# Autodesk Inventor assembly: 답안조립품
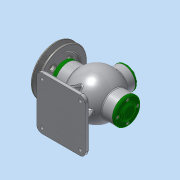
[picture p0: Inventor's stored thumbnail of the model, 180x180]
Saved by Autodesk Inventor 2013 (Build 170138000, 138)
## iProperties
Created: 2018-06
Part Number: 답안조립품
Document SubType Name: Assembly
Designer: Administrator
Author: Administrator
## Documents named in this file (19)
- C:\Users\Administrator\Desktop\480612V1001\답안조립품.iam
- C:\Users\Administrator\Desktop\480612V1001\본체.ipt
- C:\Users\Administrator\Desktop\480612V1001\V-벨트풀리.ipt
- C:\Users\Administrator\Desktop\480612V1001\너트 M8.ipt
- C:\Users\Administrator\Desktop\480612V1001\뒤커버.ipt
- C:\Users\Administrator\Desktop\480612V1001\멈춤링 15x1.ipt
- C:\Users\Administrator\Desktop\480612V1001\멈춤링 35x1.6.ipt
- 멈춤링 35x1.6.ipt
- C:\Users\Administrator\Desktop\480612V1001\베어링 6202.ipt
- 베어링 6202.ipt
- C:\Users\Administrator\Desktop\480612V1001\볼트 M4x12.ipt
- C:\Users\Administrator\Desktop\480612V1001\볼트 M4x16.ipt
- C:\Users\Administrator\Desktop\480612V1001\부시.ipt
- C:\Users\Administrator\Desktop\480612V1001\상부커버.ipt
- C:\Users\Administrator\Desktop\480612V1001\슬라이드.ipt
- C:\Users\Administrator\Desktop\480612V1001\앞커버.ipt
- C:\Users\Administrator\Desktop\480612V1001\오일 실 15 30 7.ipt
- C:\Users\Administrator\Desktop\480612V1001\키 4x4x12.ipt
- C:\Users\Administrator\Desktop\480612V1001\편심축.ipt
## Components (1 placed, 1 different names)
1. V-벨트풀리:1
